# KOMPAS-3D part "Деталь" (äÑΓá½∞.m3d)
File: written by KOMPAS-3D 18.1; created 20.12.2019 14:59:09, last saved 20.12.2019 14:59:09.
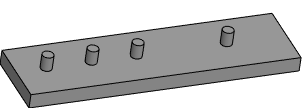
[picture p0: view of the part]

Document properties: Автор: 111; Полное имя файла: C:\Деталь.m3d

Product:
- Part/product: Деталь

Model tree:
1. Эскиз:1
2. Элемент выдавливания:1
     Расстояние 1 = 10
3. Эскиз:2  (with: Элемент выдавливания:1)
4. Элемент выдавливания:2
     Расстояние 1 = 10
5. Массив по сетке:1  (with: Элемент выдавливания:2, Эскиз:2)  (labels: v46_2_1_v98; v46_3_1_v98; v46_4_1_v98)  (4 pattern instances)
     Шаг 1 = 20; Угол раствора = 90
